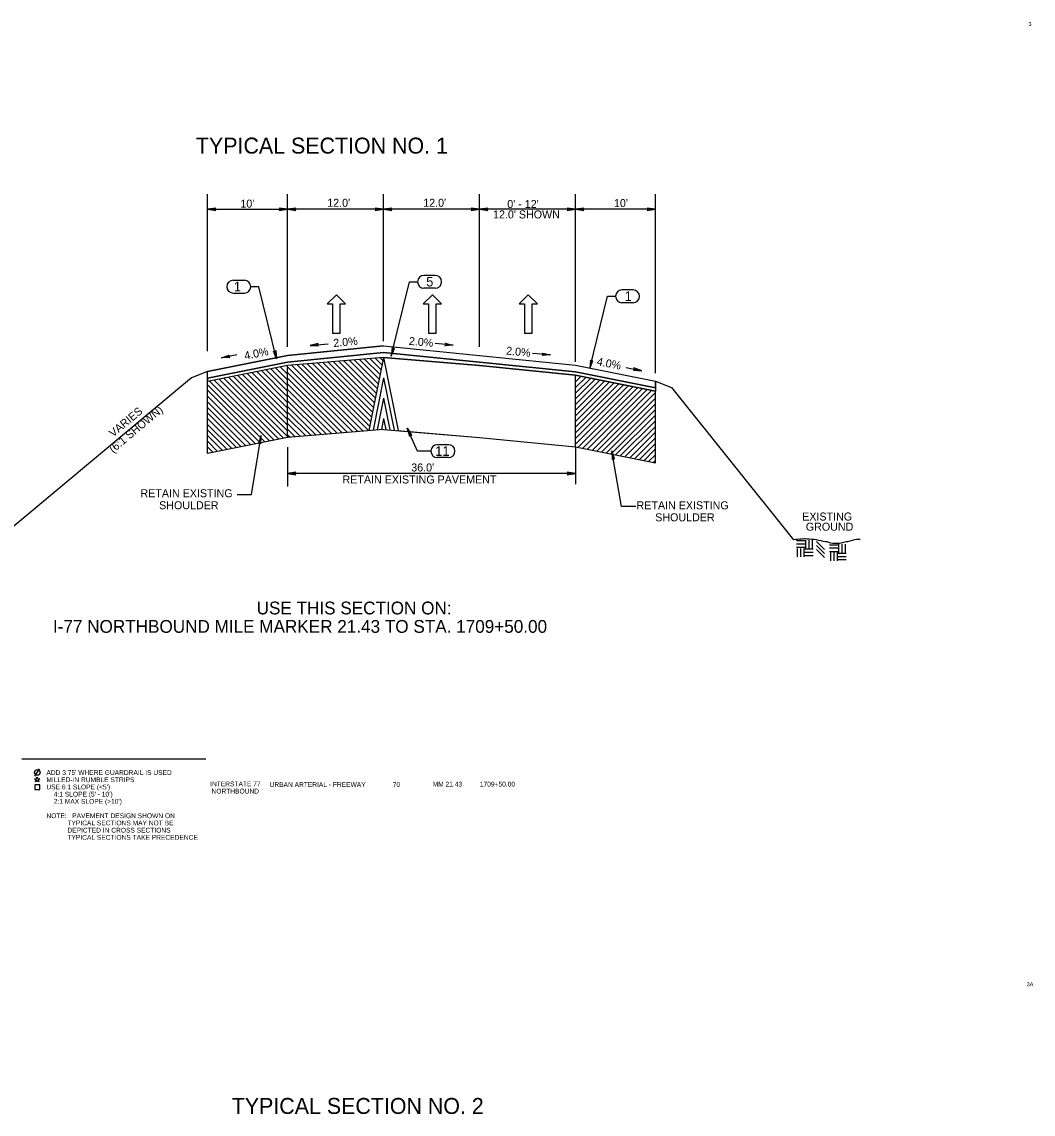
# Model space of a CAD drawing. Extents: x 2003207 to 2014043, y 843846 to 860154.
# Drawn here: x 2013655.7 to 2013782.2, y 844892.9 to 845029.4 of the extents above; entities that cross this region are included whole.
import ezdxf

# ---------------------------------------------------------------- set-up
doc = ezdxf.new("R2010")
doc.units = 0
for name, color, linetype in [('RD_EX_Road', 7, 'Continuous'), ('RD_EX_Road_txCode', 7, 'Continuous'), ('RD_QTY_Intermediate', 7, 'Continuous'), ('RD_QTY_PermVeg', 7, 'Continuous'), ('RD_QTY_Surf_Course', 7, 'Continuous'), ('RD_SHT_Bndy', 7, 'Continuous'), ('RD_SHT_TX', 7, 'Continuous'), ('RD_TX_Misc2', 7, 'Continuous'), ('RD_TX_TypSect', 7, 'Continuous'), ('RD_XS_ExGround', 7, 'Continuous')]:
    doc.layers.add(name, color=color, linetype=linetype)

msp = doc.modelspace()

# ---------------------------------------------------------------- linework, layer by layer
at = {"layer": 'RD_EX_Road'}
for p, q in [((2013688.96, 844986.44), (2013678.96, 844984.44)), ((2013687.46, 844986.14), (2013688.96, 844984.64)), ((2013688.05, 844986.26), (2013688.96, 844985.35)), ((2013700.96, 844987.44), (2013688.96, 844986.44)), ((2013688.96, 844977.45), (2013688.96, 844986.44)), ((2013688.96, 844986.27), (2013697.11, 844978.13)), ((2013689.46, 844986.48), (2013697.76, 844978.18)), ((2013690.11, 844986.54), (2013698.41, 844978.23)), ((2013690.76, 844986.59), (2013699.07, 844978.29)), ((2013691.41, 844986.65), (2013699.24, 844978.82)), ((2013692.07, 844986.7), (2013699.36, 844979.41)), ((2013692.72, 844986.76), (2013699.47, 844980)), ((2013693.37, 844986.81), (2013699.59, 844980.59)), ((2013694.02, 844986.86), (2013699.71, 844981.18)), ((2013694.68, 844986.92), (2013699.83, 844981.77)), ((2013695.33, 844986.97), (2013699.94, 844982.36)), ((2013695.98, 844987.03), (2013700.06, 844982.95)), ((2013696.64, 844987.08), (2013700.18, 844983.54)), ((2013697.29, 844987.14), (2013700.3, 844984.13)), ((2013697.94, 844987.19), (2013700.42, 844984.72)), ((2013698.59, 844987.24), (2013700.53, 844985.31)), ((2013700.96, 844987.44), (2013699.13, 844978.29)), ((2013699.25, 844987.3), (2013700.65, 844985.89)), ((2013699.9, 844987.35), (2013700.77, 844986.48)), ((2013700.55, 844987.41), (2013700.89, 844987.07)), ((2013700.96, 844987.44), (2013702.79, 844978.29)), ((2013700.96, 844987.44), (2013712.96, 844986.44)), ((2013712.96, 844986.44), (2013700.96, 844987.44)), ((2013700.96, 844987.44), (2013702.79, 844978.29)), ((2013724.96, 844985.24), (2013712.96, 844986.44)), ((2013680.98, 844984.85), (2013688.47, 844977.35)), ((2013681.57, 844984.96), (2013688.96, 844977.57)), ((2013682.16, 844985.08), (2013688.96, 844978.28)), ((2013682.75, 844985.2), (2013688.96, 844978.98)), ((2013683.33, 844985.32), (2013688.96, 844979.69)), ((2013683.92, 844985.43), (2013688.96, 844980.4)), ((2013684.51, 844985.55), (2013688.96, 844981.1)), ((2013685.1, 844985.67), (2013688.96, 844981.81)), ((2013685.69, 844985.79), (2013688.96, 844982.52)), ((2013686.28, 844985.91), (2013688.96, 844983.23)), ((2013686.87, 844986.02), (2013688.96, 844983.93)), ((2013688.96, 844985.56), (2013696.45, 844978.07)), ((2013688.96, 844984.86), (2013695.8, 844978.02)), ((2013700.96, 844984.89), (2013699.65, 844978.34)), ((2013700.96, 844984.89), (2013702.27, 844978.34)), ((2013724.96, 844976.25), (2013724.96, 844985.24)), ((2013724.96, 844985.24), (2013734.96, 844983.24)), ((2013724.96, 844976.25), (2013724.96, 844985.24)), ((2013724.96, 844985.09), (2013725.09, 844985.22)), ((2013724.96, 844984.38), (2013725.68, 844985.1)), ((2013724.96, 844983.68), (2013726.27, 844984.98)), ((2013724.96, 844982.97), (2013726.86, 844984.86)), ((2013678.96, 844975.45), (2013678.96, 844984.44)), ((2013678.96, 844984.03), (2013686.12, 844976.88)), ((2013679.21, 844984.49), (2013686.71, 844977)), ((2013679.8, 844984.61), (2013687.3, 844977.11)), ((2013680.39, 844984.73), (2013687.88, 844977.23)), ((2013688.96, 844984.15), (2013695.15, 844977.96)), ((2013688.96, 844983.44), (2013694.5, 844977.91)), ((2013724.96, 844982.26), (2013727.45, 844984.75)), ((2013724.96, 844981.55), (2013728.03, 844984.63)), ((2013724.96, 844980.85), (2013728.62, 844984.51)), ((2013724.96, 844980.14), (2013729.21, 844984.39)), ((2013724.96, 844979.43), (2013729.8, 844984.27)), ((2013724.96, 844978.73), (2013730.39, 844984.16)), ((2013724.96, 844978.02), (2013730.98, 844984.04)), ((2013724.96, 844977.31), (2013731.57, 844983.92)), ((2013724.96, 844976.6), (2013732.16, 844983.8)), ((2013725.25, 844976.19), (2013732.75, 844983.68)), ((2013725.84, 844976.07), (2013733.34, 844983.57)), ((2013726.43, 844975.95), (2013733.93, 844983.45)), ((2013678.96, 844983.33), (2013685.53, 844976.76)), ((2013678.96, 844982.62), (2013684.94, 844976.64)), ((2013688.96, 844982.74), (2013693.84, 844977.85)), ((2013700.96, 844982.34), (2013700.17, 844978.38)), ((2013700.96, 844982.34), (2013701.75, 844978.38)), ((2013727.02, 844975.83), (2013734.52, 844983.33)), ((2013727.61, 844975.72), (2013734.96, 844983.07)), ((2013728.2, 844975.6), (2013734.96, 844982.36)), ((2013734.96, 844974.25), (2013734.96, 844983.24)), ((2013678.96, 844981.91), (2013684.35, 844976.52)), ((2013678.96, 844981.2), (2013683.76, 844976.41)), ((2013688.96, 844982.03), (2013693.19, 844977.8)), ((2013688.96, 844981.32), (2013692.54, 844977.74)), ((2013728.79, 844975.48), (2013734.96, 844981.65)), ((2013729.57, 844975.56), (2013734.96, 844980.95)), ((2013678.96, 844980.5), (2013683.17, 844976.29)), ((2013678.96, 844979.79), (2013682.58, 844976.17)), ((2013688.96, 844980.61), (2013691.89, 844977.69)), ((2013688.96, 844979.91), (2013691.23, 844977.64)), ((2013700.96, 844979.79), (2013700.69, 844978.42)), ((2013700.96, 844979.79), (2013701.24, 844978.42)), ((2013729.97, 844975.25), (2013734.96, 844980.24)), ((2013730.56, 844975.13), (2013734.96, 844979.53)), ((2013678.96, 844979.08), (2013681.99, 844976.05)), ((2013678.96, 844978.38), (2013681.4, 844975.93)), ((2013688.96, 844979.2), (2013690.58, 844977.58)), ((2013688.96, 844978.49), (2013689.93, 844977.53)), ((2013700.96, 844978.45), (2013688.96, 844977.45)), ((2013700.96, 844978.45), (2013712.96, 844977.45)), ((2013702.79, 844978.29), (2013704.04, 844978.19)), ((2013703.92, 844978.62), (2013704.2, 844978.18)), ((2013704.04, 844978.19), (2013703.92, 844978.62)), ((2013704.2, 844978.18), (2013712.96, 844977.45)), ((2013731.14, 844975.01), (2013734.96, 844978.83)), ((2013731.73, 844974.89), (2013734.96, 844978.12)), ((2013678.96, 844977.67), (2013680.81, 844975.82)), ((2013688.96, 844977.45), (2013678.96, 844975.45)), ((2013678.96, 844976.96), (2013680.22, 844975.7)), ((2013688.96, 844977.79), (2013689.27, 844977.47)), ((2013712.96, 844977.45), (2013724.96, 844976.25)), ((2013712.96, 844977.45), (2013724.96, 844976.25)), ((2013732.32, 844974.77), (2013734.96, 844977.41)), ((2013732.91, 844974.66), (2013734.96, 844976.7)), ((2013678.96, 844976.26), (2013679.64, 844975.58)), ((2013678.96, 844975.55), (2013679.05, 844975.46)), ((2013724.96, 844976.25), (2013734.96, 844974.25)), ((2013729.38, 844975.36), (2013729.51, 844975.5)), ((2013733.5, 844974.54), (2013734.96, 844976)), ((2013734.09, 844974.42), (2013734.96, 844975.29)), ((2013734.68, 844974.3), (2013734.96, 844974.58))]:
    msp.add_line(p, q, dxfattribs=at)
at = {"layer": 'RD_EX_Road_txCode'}
msp.add_line((2013657.38, 844935.11), (2013657.95, 844936.05), dxfattribs=at)
for points in [[(2013657.33, 844934.79), (2013657.59, 844934.79), (2013657.67, 844935.03), (2013657.75, 844934.79), (2013658, 844934.79), (2013657.79, 844934.64), (2013657.87, 844934.4), (2013657.67, 844934.54), (2013657.46, 844934.4), (2013657.54, 844934.64)], [(2013657.37, 844933.45), (2013657.97, 844933.45), (2013657.97, 844934.05), (2013657.37, 844934.05)]]:
    msp.add_lwpolyline(points, close=True, dxfattribs=at)
msp.add_circle((2013657.67, 844935.58), 0.35, dxfattribs=at)
at = {"layer": 'RD_QTY_Intermediate'}
for p, q in [((2013700.96, 844988.06), (2013688.96, 844986.86)), ((2013700.96, 844988.06), (2013712.96, 844986.86)), ((2013688.96, 844986.86), (2013678.96, 844984.86)), ((2013688.96, 844986.44), (2013678.96, 844984.44)), ((2013700.96, 844987.44), (2013688.96, 844986.44)), ((2013688.96, 844986.17), (2013688.96, 844986.17)), ((2013700.96, 844987.44), (2013712.96, 844986.44)), ((2013712.96, 844986.86), (2013724.96, 844985.66)), ((2013712.96, 844986.44), (2013724.96, 844985.24)), ((2013678.96, 844984.86), (2013678.96, 844984.44)), ((2013724.96, 844985.66), (2013734.96, 844983.66)), ((2013724.96, 844985.24), (2013734.96, 844983.24)), ((2013734.96, 844983.66), (2013734.96, 844983.24))]:
    msp.add_line(p, q, dxfattribs=at)
msp.add_lwpolyline([(2013678.96, 844984.86), (2013688.96, 844986.86), (2013700.96, 844988.06), (2013712.96, 844986.86), (2013724.96, 844985.66), (2013734.96, 844983.66), (2013734.96, 844983.24), (2013724.96, 844985.24), (2013712.96, 844986.44), (2013700.96, 844987.44), (2013688.96, 844986.44), (2013678.96, 844984.44)], close=True, dxfattribs=at)
at = {"layer": 'RD_QTY_PermVeg'}
for p, q in [((2013676.96, 844984.89), (2013644.96, 844958.23)), ((2013678.96, 844985.69), (2013676.96, 844984.89)), ((2013734.96, 844984.49), (2013736.96, 844983.69)), ((2013736.96, 844983.69), (2013752.21, 844964.63))]:
    msp.add_line(p, q, dxfattribs=at)
at = {"layer": 'RD_QTY_Surf_Course'}
for p, q in [((2013700.96, 844988.89), (2013688.96, 844987.69)), ((2013700.96, 844988.89), (2013712.96, 844987.69)), ((2013688.96, 844987.69), (2013678.96, 844985.69)), ((2013712.96, 844987.69), (2013724.96, 844986.49)), ((2013724.96, 844986.49), (2013734.96, 844984.49)), ((2013678.96, 844984.86), (2013678.96, 844985.69)), ((2013734.96, 844983.66), (2013734.96, 844984.49))]:
    msp.add_line(p, q, dxfattribs=at)
msp.add_lwpolyline([(2013678.96, 844985.69), (2013688.96, 844987.69), (2013700.96, 844988.89), (2013712.96, 844987.69), (2013724.96, 844986.49), (2013734.96, 844984.49), (2013734.96, 844983.66), (2013724.96, 844985.66), (2013712.96, 844986.86), (2013700.96, 844988.06), (2013688.96, 844986.86), (2013678.96, 844984.86)], close=True, dxfattribs=at)
at = {"layer": 'RD_SHT_Bndy'}
msp.add_line((2013678.75, 844937.24), (2013655.75, 844937.24), dxfattribs=at)
at = {"layer": 'RD_TX_Misc2'}
for p, q in [((2013682.16, 844997.08), (2013683.56, 844997.08)), ((2013707.41, 844997.69), (2013706.01, 844997.69)), ((2013707.41, 844996.09), (2013706.01, 844996.09)), ((2013732.16, 844995.88), (2013730.76, 844995.88)), ((2013682.16, 844995.48), (2013683.56, 844995.48)), ((2013732.16, 844994.28), (2013730.76, 844994.28)), ((2013709.08, 844976.53), (2013707.68, 844976.53)), ((2013709.08, 844974.93), (2013707.68, 844974.93))]:
    msp.add_line(p, q, dxfattribs=at)
for centre, start, end in [((2013682.16, 844996.28), 90, 270), ((2013683.56, 844996.28), 270, 90), ((2013706.01, 844996.89), 90, 270), ((2013707.41, 844996.89), 270, 90), ((2013730.76, 844995.08), 90, 270), ((2013732.16, 844995.08), 270, 90), ((2013707.68, 844975.73), 90, 270), ((2013709.08, 844975.73), 270, 90)]:
    msp.add_arc(centre, 0.8, start, end, dxfattribs=at)
at = {"layer": 'RD_TX_TypSect'}
for p, q in [((2013678.96, 844988.21), (2013678.96, 845007.86)), ((2013688.96, 844988.75), (2013688.96, 845007.86)), ((2013700.96, 844989.48), (2013700.96, 845007.86)), ((2013712.96, 844988.75), (2013712.96, 845007.86)), ((2013724.96, 844986.89), (2013724.96, 845007.86)), ((2013734.96, 844985.46), (2013734.96, 845007.86)), ((2013678.96, 845005.96), (2013688.96, 845005.96)), ((2013700.96, 845005.96), (2013688.96, 845005.96)), ((2013688.96, 845005.96), (2013688.96, 845005.96)), ((2013712.96, 845005.96), (2013700.96, 845005.96)), ((2013724.96, 845005.96), (2013712.96, 845005.96)), ((2013734.96, 845005.96), (2013724.96, 845005.96)), ((2013691.77, 844988.94), (2013694.05, 844989.15)), ((2013709.68, 844988.97), (2013707.41, 844989.17)), ((2013682.63, 844987.78), (2013680.68, 844987.39)), ((2013721.85, 844987.75), (2013719.57, 844987.95)), ((2013731.29, 844986.17), (2013733.24, 844985.78)), ((2013688.96, 844976.23), (2013688.96, 844971.31)), ((2013724.96, 844976.23), (2013724.96, 844971.62)), ((2013724.96, 844972.94), (2013688.96, 844972.94))]:
    msp.add_line(p, q, dxfattribs=at)
for points in [[(2013678.96, 845005.96), (2013680, 845005.81), (2013679.84, 845005.96), (2013680, 845006.11)], [(2013688.96, 845005.96), (2013687.92, 845006.11), (2013688.08, 845005.96), (2013687.92, 845005.81)], [(2013688.96, 845005.96), (2013690, 845005.81), (2013689.84, 845005.96), (2013690, 845006.11)], [(2013700.96, 845005.96), (2013699.92, 845006.11), (2013700.08, 845005.96), (2013699.92, 845005.81)], [(2013700.96, 845005.96), (2013702, 845005.81), (2013701.84, 845005.96), (2013702, 845006.11)], [(2013712.96, 845005.96), (2013711.92, 845006.11), (2013712.08, 845005.96), (2013711.92, 845005.81)], [(2013712.96, 845005.96), (2013714, 845005.81), (2013713.84, 845005.96), (2013714, 845006.11)], [(2013724.96, 845005.96), (2013723.92, 845006.11), (2013724.08, 845005.96), (2013723.92, 845005.81)], [(2013724.96, 845005.96), (2013726, 845005.81), (2013725.84, 845005.96), (2013726, 845006.11)], [(2013734.96, 845005.96), (2013733.92, 845006.11), (2013734.08, 845005.96), (2013733.92, 845005.81)], [(2013694.58, 844990.48), (2013695.54, 844990.48), (2013695.54, 844994.15), (2013696.19, 844994.15), (2013695.06, 844995.28), (2013693.93, 844994.15), (2013694.58, 844994.15)], [(2013706.58, 844990.48), (2013707.54, 844990.48), (2013707.54, 844994.15), (2013708.19, 844994.15), (2013707.06, 844995.28), (2013705.93, 844994.15), (2013706.58, 844994.15)], [(2013718.58, 844990.48), (2013719.54, 844990.48), (2013719.54, 844994.15), (2013720.19, 844994.15), (2013719.06, 844995.28), (2013717.93, 844994.15), (2013718.58, 844994.15)], [(2013691.77, 844988.94), (2013692.82, 844988.88), (2013692.65, 844989.02), (2013692.79, 844989.18)], [(2013709.68, 844988.97), (2013708.64, 844988.91), (2013708.81, 844989.05), (2013708.66, 844989.21)], [(2013680.68, 844987.39), (2013681.67, 844987.74), (2013681.54, 844987.56), (2013681.73, 844987.45)], [(2013687.58, 844987.26), (2013687.19, 844988.23), (2013687.37, 844988.11), (2013687.48, 844988.3)], [(2013701.92, 844987.58), (2013702.31, 844988.55), (2013702.13, 844988.43), (2013702.02, 844988.62)], [(2013721.85, 844987.75), (2013720.8, 844987.69), (2013720.97, 844987.83), (2013720.83, 844987.99)], [(2013726.74, 844986.06), (2013727.14, 844987.03), (2013726.95, 844986.91), (2013726.84, 844987.1)], [(2013733.24, 844985.78), (2013732.25, 844986.13), (2013732.38, 844985.95), (2013732.19, 844985.83)], [(2013703.92, 844978.62), (2013704.2, 844977.61), (2013704.28, 844977.82), (2013704.48, 844977.73)], [(2013685.66, 844977.68), (2013685.33, 844976.68), (2013685.51, 844976.82), (2013685.63, 844976.63)], [(2013729.51, 844975.75), (2013729.54, 844974.7), (2013729.66, 844974.89), (2013729.83, 844974.75)], [(2013688.96, 844972.94), (2013690, 844972.79), (2013689.84, 844972.94), (2013690, 844973.09)], [(2013724.96, 844972.94), (2013723.92, 844973.09), (2013724.08, 844972.94), (2013723.92, 844972.79)]]:
    msp.add_lwpolyline(points, close=True, dxfattribs=at)
for points in [[(2013687.58, 844987.26), (2013685.37, 844996.28), (2013684.36, 844996.28)], [(2013701.92, 844987.58), (2013704.2, 844996.89), (2013705.21, 844996.89)], [(2013726.74, 844986.06), (2013728.95, 844995.08), (2013729.96, 844995.08)], [(2013706.88, 844975.73), (2013705.22, 844975.73), (2013703.92, 844978.62)], [(2013682.67, 844970.31), (2013684.44, 844970.31), (2013685.66, 844977.68)], [(2013732.5, 844968.8), (2013730.72, 844968.8), (2013729.51, 844975.75)]]:
    msp.add_lwpolyline(points, dxfattribs=at)
at = {"layer": 'RD_XS_ExGround'}
for p, q in [((2013753.62, 844964.52), (2013752.58, 844964.52)), ((2013753.72, 844964.62), (2013753.72, 844963.58)), ((2013754.13, 844964.62), (2013754.13, 844963.58)), ((2013754.55, 844964.62), (2013754.55, 844963.58)), ((2013756.07, 844963.43), (2013755.07, 844964.43)), ((2013753.62, 844964.11), (2013752.58, 844964.11)), ((2013753.62, 844963.69), (2013752.58, 844963.69)), ((2013752.68, 844963.58), (2013752.68, 844962.54)), ((2013753.1, 844963.58), (2013753.1, 844962.54)), ((2013753.52, 844963.58), (2013753.52, 844962.54)), ((2013754.66, 844963.48), (2013753.62, 844963.48)), ((2013754.66, 844963.06), (2013753.62, 844963.06)), ((2013756.07, 844962.93), (2013755.07, 844963.93)), ((2013756.07, 844962.43), (2013755.07, 844963.43)), ((2013757.76, 844964), (2013756.72, 844964)), ((2013757.76, 844963.59), (2013756.72, 844963.59)), ((2013757.76, 844963.17), (2013756.72, 844963.17)), ((2013756.82, 844963.07), (2013756.82, 844962.02)), ((2013757.24, 844963.07), (2013757.24, 844962.02)), ((2013757.65, 844963.07), (2013757.65, 844962.02)), ((2013758.8, 844962.96), (2013757.76, 844962.96)), ((2013757.85, 844964.1), (2013757.85, 844963.06)), ((2013758.27, 844964.1), (2013758.27, 844963.06)), ((2013758.69, 844964.1), (2013758.69, 844963.06)), ((2013754.66, 844962.65), (2013753.62, 844962.65)), ((2013758.8, 844962.54), (2013757.76, 844962.54)), ((2013758.8, 844962.13), (2013757.76, 844962.13))]:
    msp.add_line(p, q, dxfattribs=at)
msp.add_lwpolyline([(2013760.55, 844964.71), (2013760.37, 844964.71), (2013760.08, 844964.67), (2013759.89, 844964.63), (2013759.56, 844964.56), (2013759.27, 844964.49), (2013758.98, 844964.41), (2013758.8, 844964.38), (2013758.47, 844964.3), (2013758.17, 844964.23), (2013757.95, 844964.19), (2013757.77, 844964.19), (2013757.55, 844964.19), (2013757.33, 844964.19), (2013757.11, 844964.19), (2013756.89, 844964.23), (2013756.71, 844964.27), (2013756.45, 844964.38), (2013756.2, 844964.41), (2013755.9, 844964.45), (2013755.65, 844964.52), (2013755.39, 844964.56), (2013755.1, 844964.63), (2013754.81, 844964.67), (2013754.51, 844964.71), (2013754.18, 844964.74), (2013753.89, 844964.74), (2013753.67, 844964.78), (2013753.49, 844964.78), (2013753.31, 844964.74), (2013753.01, 844964.74), (2013752.76, 844964.71), (2013752.5, 844964.67), (2013752.21, 844964.63)], dxfattribs=at)

# ---------------------------------------------------------------- texts
at = {"layer": 'RD_EX_Road_txCode'}
for s, height, p in [('USE THIS SECTION ON:', 1.6, (2013685.09, 844955.33)), ('I-77 NORTHBOUND MILE MARKER 21.43 TO STA. 1709+50.00', 1.6, (2013659.63, 844953.03)), ("ADD 3.75' WHERE GUARDRAIL IS USED", 0.6, (2013658.81, 844935.27)), ('MILLED-IN RUMBLE STRIPS', 0.6, (2013658.81, 844934.37)), ("USE 6:1 SLOPE (<5')", 0.6, (2013658.81, 844933.47)), ("    4:1 SLOPE (5' - 10')", 0.6, (2013658.81, 844932.57)), ("    2:1 MAX SLOPE (>10')", 0.6, (2013658.81, 844931.67)), ('NOTE:   PAVEMENT DESIGN SHOWN ON', 0.6, (2013658.81, 844929.87)), (' TYPICAL SECTIONS MAY NOT BE ', 0.6, (2013661.21, 844928.97)), (' TYPICAL SECTIONS TAKE PRECEDENCE', 0.6, (2013661.21, 844927.17)), (' DEPICTED IN CROSS SECTIONS', 0.6, (2013661.21, 844928.07))]:
    msp.add_text(s, height=height, dxfattribs=at).set_placement(p)
at = {"layer": 'RD_SHT_TX'}
for s, height, p in [('3', 0.5, (2013781.58, 845028.87)), ('INTERSTATE 77', 0.6, (2013679.28, 844933.85)), ('URBAN ARTERIAL - FREEWAY', 0.6, (2013686.71, 844933.77)), ('70', 0.6, (2013702.11, 844933.77)), ('MM 21.43', 0.6, (2013707.1, 844933.82)), ('1709+50.00', 0.6, (2013713, 844933.82)), ('NORTHBOUND', 0.6, (2013679.45, 844932.95)), ('3A', 0.5, (2013781.36, 844908.87))]:
    msp.add_text(s, height=height, dxfattribs=at).set_placement(p)
at = {"layer": 'RD_TX_Misc2'}
for s, p in [('5', (2013706.29, 844996.31)), ('1', (2013682.25, 844995.69)), ('1', (2013731.1, 844994.49)), ('11', (2013707.42, 844975.14))]:
    msp.add_text(s, height=1.2, dxfattribs=at).set_placement(p)
at = {"layer": 'RD_TX_TypSect'}
for s, height, p in [('TYPICAL SECTION NO. 1', 2, (2013677.5, 845012.91)), ("10'", 1, (2013683.06, 845006.16)), ("12.0'", 1, (2013693.92, 845006.26)), ("12.0'", 1, (2013705.92, 845006.26)), ("0' - 12'", 1, (2013716.43, 845006.11)), ("10'", 1, (2013729.77, 845006.23)), ("12.0' SHOWN", 1, (2013714.65, 845004.81)), ("36.0'", 1, (2013704.42, 844973.19)), ('RETAIN EXISTING PAVEMENT', 1, (2013695.83, 844971.69)), ('RETAIN EXISTING', 1, (2013670.57, 844969.97)), (' SHOULDER', 1, (2013672.53, 844968.47)), ('RETAIN EXISTING', 1, (2013732.59, 844968.46)), (' SHOULDER', 1, (2013734.55, 844966.96)), ('EXISTING', 1, (2013753.3, 844967.06)), ('GROUND', 1, (2013753.75, 844965.79)), ('TYPICAL SECTION NO. 2', 2, (2013681.98, 844892.91))]:
    msp.add_text(s, height=height, dxfattribs=at).set_placement(p)
for s, rotation, p in [('2.0%', 5.2184, (2013694.72, 844988.74)), ('2.0%', 354.7816, (2013704.09, 844989.02)), ('4.0%', 11.3099, (2013683.65, 844987.15)), ('2.0%', 354.7816, (2013716.25, 844987.8)), ('4.0%', 348.6901, (2013727.56, 844986.49)), ('VARIES', 39.8056, (2013667.16, 844977.42)), ('(6:1 SHOWN)', 39.8056, (2013667.15, 844975.45))]:
    msp.add_text(s, height=1, rotation=rotation, dxfattribs=at).set_placement(p)

doc.saveas('drawing.dxf')
